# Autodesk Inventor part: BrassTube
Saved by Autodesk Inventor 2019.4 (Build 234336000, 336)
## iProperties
Created: 2020-04
Part Number: BrassTube
Material: Generic
Document SubType Name: Modeling
Designer: Administrator
Density: 1 g/cm^3
Appearance: Default
Title: BrassTube v3
Author: Administrator
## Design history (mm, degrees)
feature "Body1"
body "Solid1"
